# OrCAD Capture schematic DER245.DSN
size C; title: 44W 12V; rev: 3; note: MITSUMI
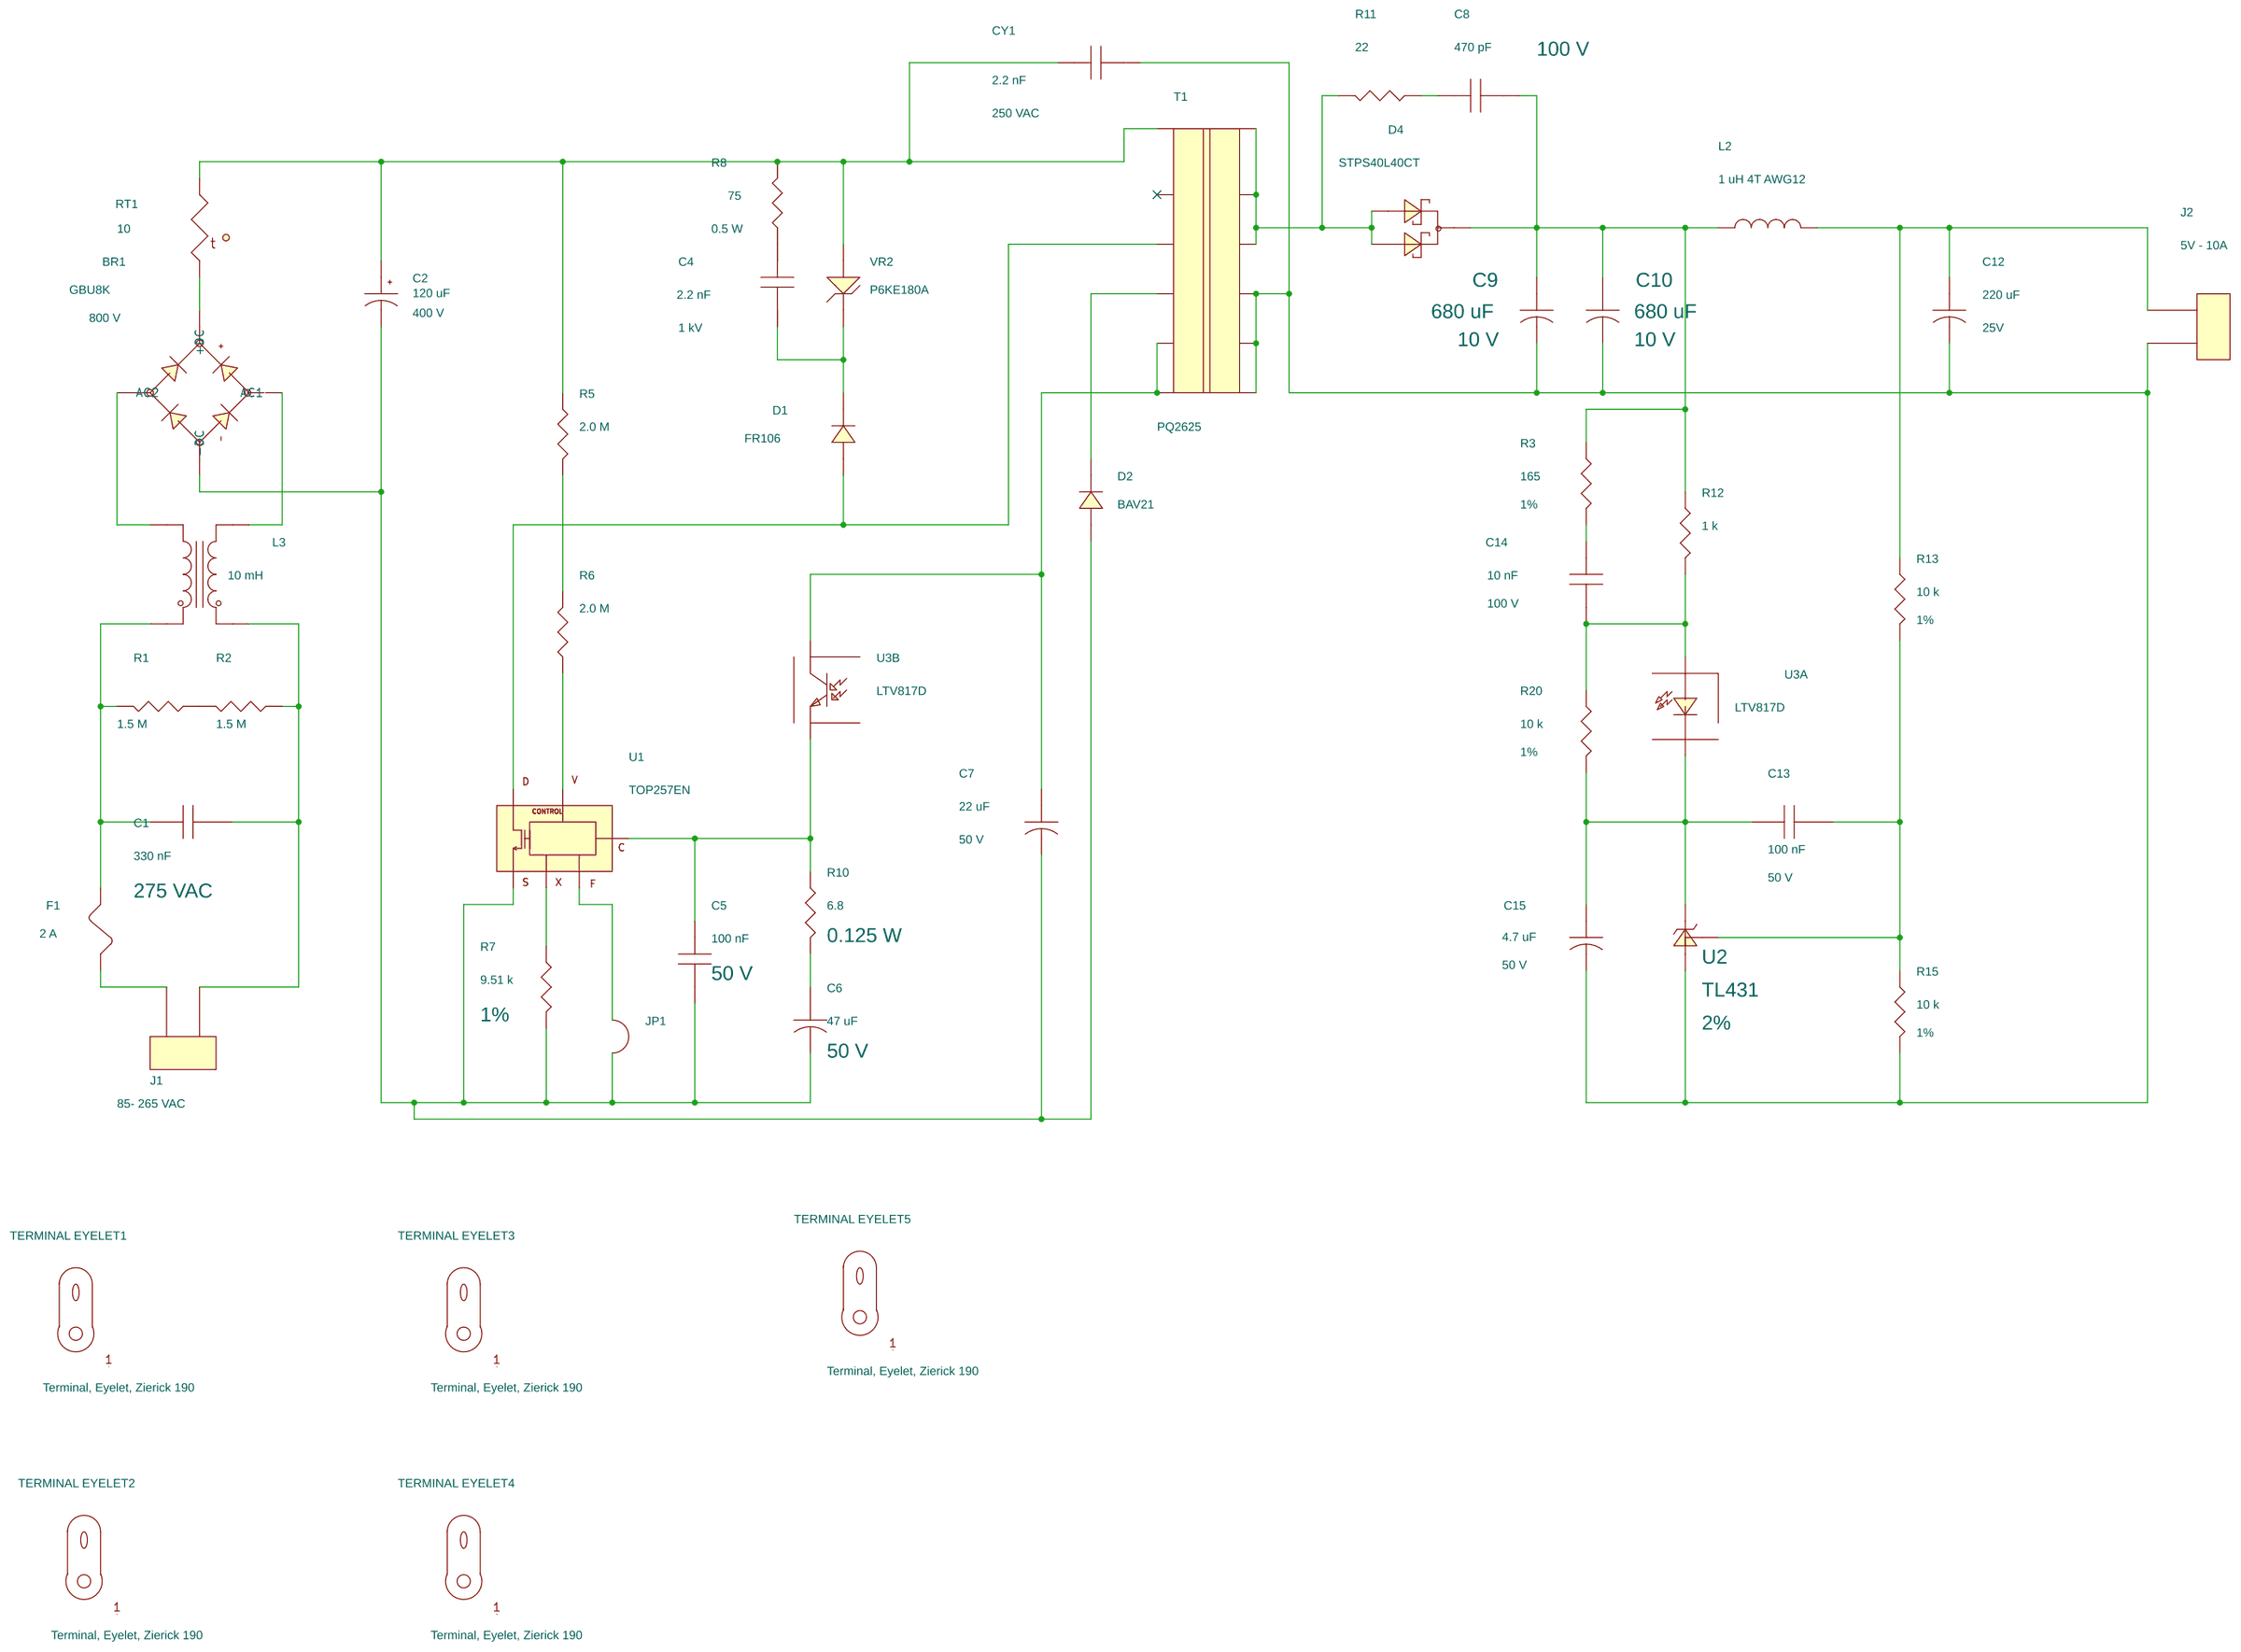
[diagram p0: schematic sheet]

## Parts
BR1  GBU8K  [pidaxbridgegbu8]
C1  330 nF  [pinpcaprad550x395490030]
C2  120 uF  [pipolcapclyd710ls300040]
C4  2.2 nF  [pinpcaprad350x100200030]
C5  100 nF  [pinpcaprad200x100200030]
C6  47 uF  [pipolcapcyld250ls100030]
C7  22 uF  [pipolcapcyld250ls100030]
C8  470 pF  [pinpcaprad200x100100030]
C9  680 uF  [PI_POLCAP_CYL/D.400/LS.200/.040]
C10  680 uF  [PI_POLCAP_CYL/D.400/LS.200/.040]
C12  220 uF  [pipolcapclyd320ls140030]
C13  100 nF  [PI_NP_CAP/RAD/.200X.100/.200/.030]
C14  10 nF  [PI_NP_CAP/RAD/.200X.100/.100/.030]
C15  4.7 uF  [PI_POLCAP_CLY/D.200/LS.80/.030]
CY1  2.2 nF  [pinpycaprad540x290ls400040]
D1  FR106  [pidv200x110x040do41]
D2  BAV21  [pidv200x080x030do35]
D4  STPS40L40CT  [PI_DV/TO220_3/VF1]
F1  2 A  [PI_TR5_SUBMIN_FUSE]
J1  85- 265 VAC  [pihdr2pin312]
J2  5V - 10A  [pihdr2pin312]
JP1  J  [PI_JUMPER200]
L2  1 uH 4T AWG12  [pi_choke_coilcraft_rfb0807]
L3  10 mH  [PI_TOROID_BALUN_1]
R1  1.5 M  [pi14wvresd100ls200d030]
R2  1.5 M  [pi14wvresd100ls200d030]
R3  165  [PI_1/4W_VRES/D.100/LS100/.030]
R5  2.0 M  [pi14wvresd100ls100d030]
R6  2.0 M  [pi14wresd100ls400d030]
R7  9.51 k  [PI_1/4W_VRES/D.100/LS100/.030]
R8  75  [pi12wvresd180ls150d040]
R10  6.8  [pi18wvresd80ls100d030]
R11  22  [PI_1/4W_VRES/D.100/LS100/.030]
R12  1 k  [PI_1/4W_VRES/D.100/LS100/.030]
R13  10 k  [PI_1/4W_VRES/D.100/LS100/.030]
R15  10 k  [PI_1/4W_VRES/D.100/LS100/.030]
R20  10 k  [PI_1/4W_VRES/D.100/LS100/.030]
RT1  10  [PI_RAD/.400X.175/LS.250/.031]
T1  PQ2625  [PI_BOBBIN_BPQ26_20_12P]
TERMINAL EYELET1  Terminal, Eyelet, Zierick 190  [pizierick190eyelet]
TERMINAL EYELET2  Terminal, Eyelet, Zierick 190  [pizierick190eyelet]
TERMINAL EYELET3  Terminal, Eyelet, Zierick 190  [pizierick190eyelet]
TERMINAL EYELET4  Terminal, Eyelet, Zierick 190  [pizierick190eyelet]
TERMINAL EYELET5  Terminal, Eyelet, Zierick 190  [pizierick190eyelet]
U1  TOP257EN  [PI_IC/ESIP7/6-TH]
U2  TL431  [PITO92R100]
U3  LTV817D  [pi_dip4]  (sections A,B)
VR2  P6KE180A  [pidv200x140x050do15do204ac]

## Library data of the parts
BR1 = DISCRETE_BRIDGE_+~~-: Disp_Voltage: 800 V; Part Number: 15-00347-00
C1 = CAP_NP: Disp_Voltage: 275 VAC; FPLIST: PI_NP_CAP/RAD/.550X.395/.490/.030,PI_NP_CAP/RAD/.550X.395/.490/.030_HORZ; PCB Editor PCBFP: pinpcaprad550x395490030,pinpcaprad550x395490030horz; Part Number: 20-00642-00; Tol: 20
C2 = CAPACITOR_POL: Disp_Voltage: 400 V; FPLIST: PI_POLCAP_CLY/D.710/LS.300/.040,PI_POLCAP_CLY/D.710/LS.300/.040_1.400L_HORIZ; PCB Editor PCBFP: pipolcapclyd710ls300040,pipolcapd710ls3000401400lhoriz; Part Number: 20-00685-00; Tol: 20
C4 = CAP_NP: Disp_Voltage: 1 kV; Part Number: 20-00357-00; Tol: 10
C5 = CAP_NP: Disp_Voltage: 50 V; Part Number: 20-00771-00; Tol: 10
C6 = CAP_POL: Disp_Voltage: 50 V; Part Number: 20-00444-00; Tol: 20
C7 = CAP_POL: Disp_Voltage: 50 V; Part Number: 20-00056-00; Tol: 20
C8 = CAP_NP: COMPGROUP: 2; Disp_Voltage: 100 V; Part Number: 20-00310-00; Tol: 10
C9 C10 = CAP_POL: Disp_Voltage: 10 V; PCB Editor PCBFP: pipolcapcyld400ls200040; Part Number: 20-00825-00
C12 = CAP_POL: Disp_Voltage: 25V; Part Number: 20-00028-00; Tol: 20
C13 = CAP_NP: Disp_Voltage: 50 V; PCB Editor PCBFP: pinpcaprad200x100200030; Part Number: 20-00771-00
C14 = CAP_NP: Disp_Voltage: 100 V; PCB Editor PCBFP: pinpcaprad200x100100030; Part Number: 20-00318-00
C15 = CAP_POL: Disp_Voltage: 50 V; FPLIST: PI_POLCAP_CLY/D.200/LS.80/.030,PI_POLCAP_CLY/D.200/LS.80/.030_H; PCB Editor PCBFP: pipolcapclyd200ls80030,pipolcapclyd200ls80030h; Part Number: 20-00442-00
CY1 = CAP_NP: Disp_Voltage: 250 VAC; Part Number: 20-00376-00; Tol: 20
D1 = DIODE: ALT_SYMBOLS: pidax475x125040do41,pidv200x110x040do41wbead,pidax390x125040do41; FPLIST: PI_DV/.200X.110X.040/DO_41,PI_DAX/.475X.125/.040/DO_41,PI_DV/.200X.110X.040/DO_41_WBEAD,PI_DAX/.390X.125/.040/DO_41; Part Number: 15-00426-00
D2 = DIODE: ALT_SYMBOLS: pidax375x070030do35,pidv100x080x030do35; FPLIST: PI_DV/.200X.080X.030/DO_35,PI_DAX/.375X.070/.030/DO_35,PI_DV/.100X.080X.030/DO_35; Part Number: 15-00084-00
D4 = DS_DUAL_CK_AKA: FPLIST: PI_DV/TO220_3/VF1,PI_DV/TO220_3; Part Number: 15-00360-00
F1 = FUSE: Part Number: 40-00002-00; Voltage: 250 V
J1 J2 = CON2: Part Number: 35-00063-00
JP1 = JUMPER_1: PCB Editor PCBFP: pi_jumper200; Part Number: 65-00001-00
L2 = INDUCTOR: Part Number: 30-00161-00; Tol: 0.2
L3 = INDUCTOR_4P: Part Number: 32-00016-00
R1 R2 = R: ALT_SYMBOLS: pi14wvresd100ls200d030,pi14wresd100ls400d030,pi14wresd100ls500d030; FPLIST: pi14wvresd100ls100d030,pi14wvresd100ls200d030,pi14wresd100ls400d030,pi14wresd100ls500d030; PCB Editor PCBFP: pi14wvresd100ls100d030,pi14wvresd100ls200d030,pi14wresd100ls400d030,pi14wresd100ls500d030; Part Number: 05-03107-00; Tol: 5%
R3 = R: Disp_Tol: 1%; FPLIST: PI_1/4W_VRES/D.100/LS100/.030,PI_1/4W_VRES/D.100/LS200/.030,PI_1/4W_RES/D.100/LS.400/.030,PI_1/4W_RES/D.100/LS.500/.030; PCB Editor PCBFP: pi14wvresd100ls100d030,pi14wvresd100ls200d030,pi14wresd100ls400d030,pi14wresd100ls500d030; Part Number: 05-01901-00
R5 R6 = R: ALT_SYMBOLS: pi14wvresd100ls200d030,pi14wresd100ls400d030,pi14wresd100ls500d030; FPLIST: pi14wvresd100ls100d030,pi14wvresd100ls200d030,pi14wresd100ls400d030,pi14wresd100ls500d030; PCB Editor PCBFP: pi14wvresd100ls100d030,pi14wvresd100ls200d030,pi14wresd100ls400d030,pi14wresd100ls500d030; Part Number: 05-03110-00; Tol: 5%
R7 = R: ALT_SYMBOLS: pi14wvresd100ls200d030,pi14wresd100ls400d030,pi14wresd100ls500d030; Disp_Tol: 1%; FPLIST: PI_1/4W_VRES/D.100/LS100/.030,PI_1/4W_VRES/D.100/LS200/.030,PI_1/4W_RES/D.100/LS.400/.030,PI_1/4W_RES/D.100/LS.500/.030; PCB Editor PCBFP: pi14wvresd100ls100d030,pi14wvresd100ls200d030,pi14wresd100ls400d030,pi14wresd100ls500d030; Part Number: 05-02070-00; Tol: 1%
R8 = R: ALT_SYMBOLS: pi12wvresd180ls200d040,pi12wvresd180ls250d040,pi12wresd180ls675d040; Disp_Power: 0.5 W; FPLIST: pi12wvresd180ls150d040,pi12wvresd180ls200d040,pi12wvresd180ls250d040,pi12wresd180ls675d040; Part Number: 05-02648-00; Tol: 5%
R10 = R: ALT_SYMBOLS: pi18wresd080ls300d030; Disp_Power: 0.125 W; FPLIST: PI_1/8W_VRES/D.80/LS100/.030,PI_1/8W_RES/D.080/LS.300/.030; PCB Editor PCBFP: pi18wvresd80ls100d030,pi18wresd080ls300d030; Part Number: 05-02285-00; Tol: 5%
R11 = R: FPLIST: PI_1/4W_VRES/D.100/LS100/.030,PI_1/4W_VRES/D.100/LS200/.030,PI_1/4W_RES/D.100/LS.400/.030,PI_1/4W_RES/D.100/LS.500/.030; PCB Editor PCBFP: pi14wvresd100ls100d030,pi14wvresd100ls200d030,pi14wresd100ls400d030,pi14wresd100ls500d030; Part Number: 05-02467-00
R12 = R: FPLIST: PI_1/4W_VRES/D.100/LS100/.030,PI_1/4W_VRES/D.100/LS200/.030,PI_1/4W_RES/D.100/LS.400/.030,PI_1/4W_RES/D.100/LS.500/.030; PCB Editor PCBFP: pi14wvresd100ls100d030,pi14wvresd100ls200d030,pi14wresd100ls400d030,pi14wresd100ls500d030; Part Number: 05-02507-00
R13 R15 R20 = R: Disp_Tol: 1%; FPLIST: PI_1/4W_VRES/D.100/LS100/.030,PI_1/4W_VRES/D.100/LS200/.030,PI_1/4W_RES/D.100/LS.400/.030,PI_1/4W_RES/D.100/LS.500/.030; PCB Editor PCBFP: pi14wvresd100ls100d030,pi14wvresd100ls200d030,pi14wresd100ls400d030,pi14wresd100ls500d030; Part Number: 05-02072-00
RT1 = THERMISTOR: Part Number: 90-00012-00
T1 = BPQ26_20_12P_GENERIC: Part Number: 25-00025-00
TERMINAL EYELET1-TERMINAL EYELET5 = Terminal_Eyelet: Part Number: 60-00016-00
U1 = TOP25X_E: Part Number: 10-00271-00
U2 = TL431_TO: FPLIST: PITO92R100,PIT092100; Part Number: 45-00002-00; Tol: 2%
U3 = OPTO_A_B: Part Number: 53-00019-00; COMPGROUP: 2
VR2 = DIODE_ZENER: ALT_SYMBOLS: pidax550x140050do15do204ac; FPLIST: PI_DV/.200X.140X.050/DO_15/DO_204AC,PI_DAX/.550X.140/.050/DO_15/DO_204AC; Part Number: 15-00405-00

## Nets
N28552: C12.1 J2.1 L2.2 R13.1
N36865: C9.2 C10.2 C12.2 C15.2 CY1.2 J2.2 R15.2 T1.7 T1.8 T1.9 U2.2(A)
N70743: C13.2 R13.2 R15.1 U2.1(VREF)
N154004: C5.1 R10.1 U1.3(C) U3.3(E)
N155104: R7.2 U1.2(X)
N159266: BR1.4(-DC) C2.2 C5.2 C6.2 C7.2 D2.2 JP1.2 R7.1 U1.5(S)
N164818: D1.2 T1.3 U1.7(D)
N168193: C2.1 CY1.1 R5.1 R8.1 RT1.1 T1.1 VR2.2
N172409: R5.2 R6.1
N228418: C1.2 J1.1 L3.2 R2.2
N376837: R6.2 U1.1(V)
N627574: C7.1 T1.5 T1.6 U3.4(C)
N674093: C1.1 F1.2 L3.3 R1.1
N1001047: C14.2 R12.2 R20.1 U3.1(A)
N1033544: C8.2 C9.1 C10.1 D4.2(CATHODE) L2.1 R3.1 R12.1
N1051058: D4.1(A1) D4.3(A2) R11.2 T1.10 T1.11 T1.12
N1062136: D2.1 T1.4
N1093917: C13.1 C15.1 R20.2 U2.3(C) U3.2(C)
N1098974: C6.1 R10.2
N1101802: JP1.1 U1.4(F)
N1107832: F1.1 J1.2
N1118812: C4.2 D1.1 VR2.1
N1135250: BR1.1(+DC) RT1.2
N1147016: BR1.3(AC2) L3.4
N1147329: BR1.2(AC1) L3.1
N1169234: C14.1 R3.2
N1179142: C8.1 R11.1
N1183772: R1.2 R2.1
N1183773: C4.1 R8.2

Not connected (* = marked no-connect by the designer): T1 2*; TERMINAL EYELET1 1; TERMINAL EYELET2 1; TERMINAL EYELET3 1; TERMINAL EYELET4 1; TERMINAL EYELET5 1
